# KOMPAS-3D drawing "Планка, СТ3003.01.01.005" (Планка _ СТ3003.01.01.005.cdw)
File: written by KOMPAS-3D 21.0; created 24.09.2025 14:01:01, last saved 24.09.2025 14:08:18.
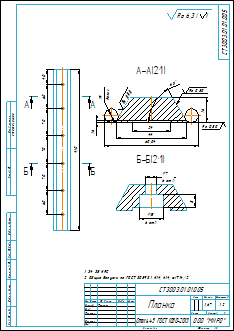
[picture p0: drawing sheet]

Sheet 1: A3, portrait

Document properties: Полное имя файла: C:\Users\1\Yandex.Disk\Документы\Новая папка\Стапель №2\Стапель _ СТ3003.00.00.000\Опора _ СТ3003.01.00.000\2D\Кронштейн _ СТ3003.01.01.000\Планка _ СТ3003.01.01.005.cdw; Знак неуказанной шероховатости: 4; Параметр неуказанной шероховатости: Ra 6,3; Масса: 1.670176

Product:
- Part/product: Планка  | designation СТ3003.01.01.005
    Материал: Сталь 45  ГОСТ 1050-2013 (density 7810 kg/m3)
    Масса: 1.670176

Title block, sheet 1: Наименование: Планка; designation: СТ3003.01.01.005; Материал: Сталь 45  ГОСТ 1050-2013; Масса: 1,67; Количество листов документа: 1; organisation: ООО "МИРО"; Форматы листов документа: A3; Разработал: Тимонин

Views: Вид 1, Вид:1, Разрез А-А, Разрез 3, Разрез Б-Б
Referenced files in C:\Users\1\Yandex.Disk\Документы\Новая папка\Стапель №2\Стапель _ СТ3003.00.00.000\Опора _ СТ3003.01.00.000\3D\Кронштейн _ СТ3003.01.01.000\: Планка _ СТ3003.01.01.005.m3d
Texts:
  Ra 0,80
  Ролик
  Ra 6,3
  Ra 6,3 ( )
  СТ3003.01.01.000
  СТ3003.01.01.005 Планка
Dimensions and other numbers on the sheet: 40; 60; 70; 410; 44; 24; 60,04; 16; 1,6; 9; 15; 6 отв.; 7; 8; 1:2; 1; 1,67

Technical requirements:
  34...38 HRC.
  Общие допуски по ГОСТ 30893.1: Н14, h14, ± IT14/2.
